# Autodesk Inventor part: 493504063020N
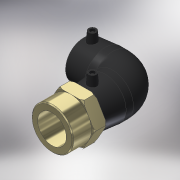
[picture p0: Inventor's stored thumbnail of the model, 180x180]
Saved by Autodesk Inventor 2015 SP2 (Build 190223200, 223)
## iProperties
Created: 2017-06
Part Number: 493504063020N
Material: Generic
Description: PLASSON 90° ELBOW FEMALE TRANSITION 63 x 2''
Document SubType Name: Modeling
Designer: KIM
Mass: 623.638 g
Surface Area: 1137.86 cm^2
Volume: 623.638 cm^3
Density: 1 g/cm^3
Appearance: Rubber - Black
Author: KIM
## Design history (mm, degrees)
derived "493504.ipt"
feature "Solid1::493504.ipt"
tag "TaggingFeature1"
body "Solid1"
other parameters: "d2" = 82, "d4" = 43.66667, "d5" = 73.8, "d8" = 168 deg, "d10" = 23.2, "d11" = 7.73333, "d29" = 57, "d30" = 15, "d31" = 72.05, "d34" = 5 deg, "d41" = 4, "d42" = 14, "d43" = 0, "d49" = 63, "d50" = 53.55, "d51" = 23.2, "d52" = 58, "d54" = 90 deg, "d57" = 63, "d58" = 58, "d59" = 0, "d61" = 90 deg, "d86" = 3, "d87" = 0, "d93" = 0.1, "d96" = 56.656, "d97" = 49, "d98" = 62, "d99" = 82, "d100" = 49.6, "d107" = 24.8, "d108" = 0, "d109" = 1.89, "d112" = 45 deg, "d113" = 45 deg, "d114" = 3.15, "d_" = 63, "L_" = 193, "L_1" = 58, "D_" = 49, "A_" = 57, "d_2" = 12, "L_2" = 62, "D_1" = 82, "Rp_" = 56.656
